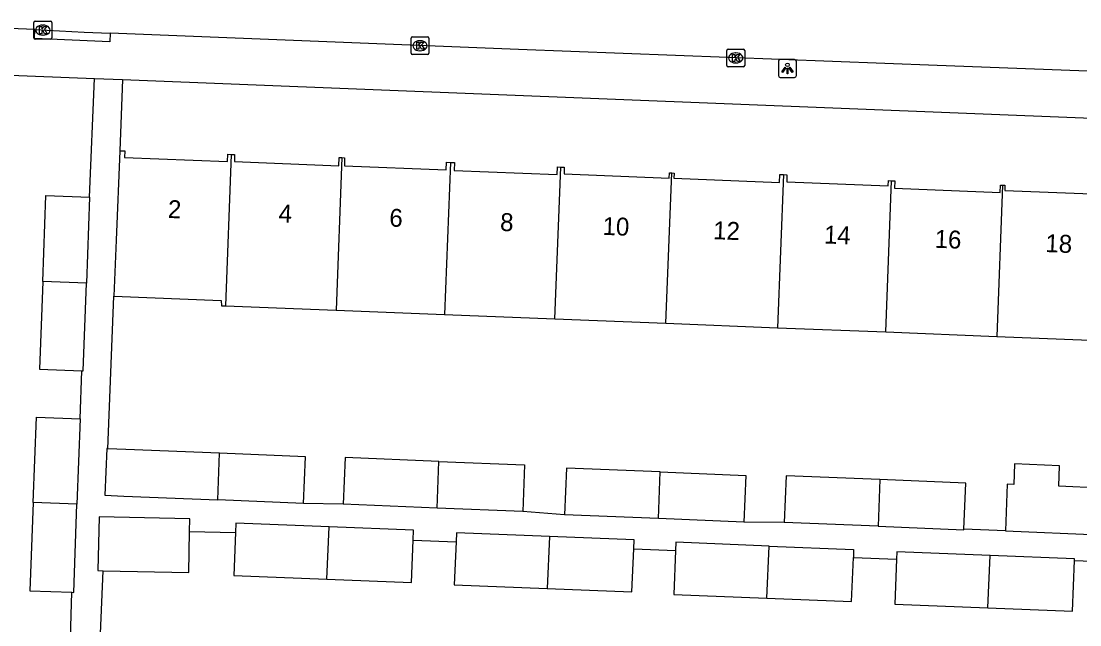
# Model space of a CAD drawing. Extents: x 160077 to 160945, y 386481 to 387498.
# Drawn here: x 160704.4 to 160763.6, y 386637.3 to 386671 of the extents above; entities that cross this region are included whole.
import ezdxf

# ---------------------------------------------------------------- set-up
doc = ezdxf.new("R2010")
doc.units = 0
for name, color, linetype in [('IMGEO_Kolk', 7, 'Continuous'), ('IMGEO_Lichtpunt', 7, 'Continuous'), ('IMGEO_Pand', 7, 'Continuous'), ('IMGEO_Pand_nummerreeks', 7, 'Continuous'), ('IMGEO_Rijbaan_lokaal_open', 7, 'Continuous'), ('IMGEO_Voetpad_open', 7, 'Continuous')]:
    doc.layers.add(name, color=color, linetype=linetype)

msp = doc.modelspace()

# ---------------------------------------------------------------- linework, layer by layer
at = {"layer": 'IMGEO_Kolk'}
for p, q in [((160705.154, 386670.106), (160705.154, 386670.958)), ((160705.229, 386671.032), (160706.081, 386671.032)), ((160705.642, 386670.812), (160705.667, 386670.812)), ((160706.155, 386670.958), (160706.155, 386670.106)), ((160705.665, 386670.252), (160705.64, 386670.252)), ((160726.213, 386669.238), (160726.213, 386670.09)), ((160726.288, 386670.164), (160727.14, 386670.164)), ((160727.214, 386670.09), (160727.214, 386669.238)), ((160706.081, 386670.032), (160705.229, 386670.032)), ((160726.701, 386669.944), (160726.726, 386669.944)), ((160743.922, 386669.479), (160744.774, 386669.479)), ((160727.14, 386669.164), (160726.288, 386669.164)), ((160726.724, 386669.384), (160726.699, 386669.384)), ((160743.847, 386668.553), (160743.847, 386669.405)), ((160744.335, 386669.259), (160744.36, 386669.259)), ((160744.848, 386669.405), (160744.848, 386668.553)), ((160744.774, 386668.479), (160743.922, 386668.479)), ((160744.358, 386668.699), (160744.333, 386668.699))]:
    msp.add_line(p, q, dxfattribs=at)
for points in [[(160705.154, 386670.106), (160705.154, 386670.958)], [(160705.229, 386671.032), (160706.081, 386671.032)], [(160705.475, 386670.732), (160705.598, 386670.732), (160705.598, 386670.581), (160705.728, 386670.732), (160705.892, 386670.732), (160705.746, 386670.581), (160705.899, 386670.332), (160705.747, 386670.332), (160705.662, 386670.496), (160705.598, 386670.429), (160705.598, 386670.332), (160705.475, 386670.332), (160705.475, 386670.732)], [(160706.155, 386670.958), (160706.155, 386670.106)], [(160726.213, 386669.238), (160726.213, 386670.09)], [(160726.288, 386670.164), (160727.14, 386670.164)], [(160727.214, 386670.09), (160727.214, 386669.238)], [(160706.081, 386670.032), (160705.229, 386670.032)], [(160726.534, 386669.864), (160726.657, 386669.864), (160726.657, 386669.713), (160726.787, 386669.864), (160726.951, 386669.864), (160726.805, 386669.713), (160726.958, 386669.464), (160726.806, 386669.464), (160726.721, 386669.628), (160726.657, 386669.561), (160726.657, 386669.464), (160726.534, 386669.464), (160726.534, 386669.864)], [(160743.922, 386669.479), (160744.774, 386669.479)], [(160727.14, 386669.164), (160726.288, 386669.164)], [(160743.847, 386668.553), (160743.847, 386669.405)], [(160744.168, 386669.179), (160744.291, 386669.179), (160744.291, 386669.028), (160744.421, 386669.179), (160744.585, 386669.179), (160744.439, 386669.028), (160744.592, 386668.779), (160744.44, 386668.779), (160744.355, 386668.943), (160744.291, 386668.876), (160744.291, 386668.779), (160744.168, 386668.779), (160744.168, 386669.179)], [(160744.848, 386669.405), (160744.848, 386668.553)], [(160744.774, 386668.479), (160743.922, 386668.479)]]:
    msp.add_lwpolyline(points, dxfattribs=at)
for centre, start, end in [((160705.231, 386670.956), 91.55205, 178.44795), ((160705.231, 386670.956), 91.55205, 178.44795), ((160706.079, 386670.956), 1.55205, 88.44795), ((160706.079, 386670.956), 1.55205, 88.44795), ((160705.231, 386670.108), 181.55205, 268.44795), ((160705.231, 386670.108), 181.55205, 268.44795), ((160706.079, 386670.108), 271.55205, 358.44795), ((160706.079, 386670.108), 271.55205, 358.44795), ((160726.29, 386670.088), 91.55205, 178.44795), ((160726.29, 386670.088), 91.55205, 178.44795), ((160727.138, 386670.088), 1.55205, 88.44795), ((160727.138, 386670.088), 1.55205, 88.44795), ((160743.924, 386669.403), 91.55205, 178.44795), ((160743.924, 386669.403), 91.55205, 178.44795), ((160744.772, 386669.403), 1.55205, 88.44795), ((160744.772, 386669.403), 1.55205, 88.44795), ((160726.29, 386669.24), 181.55205, 268.44795), ((160726.29, 386669.24), 181.55205, 268.44795), ((160727.138, 386669.24), 271.55205, 358.44795), ((160727.138, 386669.24), 271.55205, 358.44795), ((160743.924, 386668.555), 181.55205, 268.44795), ((160743.924, 386668.555), 181.55205, 268.44795), ((160744.772, 386668.555), 271.55205, 358.44795), ((160744.772, 386668.555), 271.55205, 358.44795)]:
    msp.add_arc(centre, 0.0765, start, end, dxfattribs=at)
for centre, major_axis, ratio, start_param, end_param in [((160705.641, 386670.532), (-0.387, 0.002), 0.722429, 4.712389, 7.853982), ((160705.666, 386670.532), (-0.39, 0.002), 0.717154, 1.570796, 4.712389), ((160726.7, 386669.664), (-0.387, 0.002), 0.722429, 4.712389, 7.853982), ((160726.725, 386669.664), (-0.39, 0.002), 0.717154, 1.570796, 4.712389), ((160744.334, 386668.979), (-0.387, 0.002), 0.722429, 4.712389, 7.853982), ((160744.359, 386668.979), (-0.39, 0.002), 0.717154, 1.570796, 4.712389)]:
    msp.add_ellipse(centre, major_axis=major_axis, ratio=ratio, start_param=start_param, end_param=end_param, dxfattribs=at)
at = {"layer": 'IMGEO_Lichtpunt'}
for p, q in [((160747.638, 386668.893), (160746.83, 386668.893)), ((160747.638, 386668.893), (160746.83, 386668.893)), ((160746.736, 386668.798), (160746.736, 386667.991)), ((160746.736, 386668.798), (160746.736, 386667.991)), ((160747.732, 386667.991), (160747.732, 386668.798)), ((160747.732, 386667.991), (160747.732, 386668.798)), ((160746.83, 386667.897), (160747.638, 386667.897)), ((160746.83, 386667.897), (160747.638, 386667.897))]:
    msp.add_line(p, q, dxfattribs=at)
for points in [[(160747.11, 386668.462), (160747.149, 386668.434), (160746.961, 386668.172), (160746.923, 386668.199), (160747.11, 386668.462)], [(160747.212, 386668.414), (160747.259, 386668.414), (160747.259, 386668.092), (160747.212, 386668.092), (160747.212, 386668.414)], [(160747.322, 386668.434), (160747.36, 386668.461), (160747.547, 386668.199), (160747.508, 386668.171), (160747.322, 386668.434)]]:
    msp.add_lwpolyline(points, dxfattribs=at)
msp.add_circle((160747.235, 386668.596), 0.0994, dxfattribs=at)
for centre, start, end in [((160746.83, 386668.798), 90, 180), ((160746.83, 386668.798), 90, 180), ((160747.638, 386668.798), 0, 90), ((160747.638, 386668.798), 0, 90), ((160746.83, 386667.991), 180, 270), ((160746.83, 386667.991), 180, 270), ((160747.638, 386667.991), 270, 0), ((160747.638, 386667.991), 270, 360)]:
    msp.add_arc(centre, 0.0946, start, end, dxfattribs=at)
at = {"layer": 'IMGEO_Pand'}
for points in [[(160709.948, 386663.799), (160709.748, 386658.803), (160709.624, 386655.676)], [(160709.948, 386663.799), (160710.224, 386663.788), (160710.21, 386663.426), (160715.964, 386663.197), (160715.98, 386663.605), (160716.172, 386663.598)], [(160716.172, 386663.598), (160715.845, 386655.138)], [(160716.172, 386663.598), (160716.364, 386663.59), (160716.348, 386663.197), (160722.191, 386662.964), (160722.209, 386663.427), (160722.358, 386663.418)], [(160722.358, 386663.418), (160722.028, 386654.895)], [(160722.358, 386663.418), (160722.506, 386663.409), (160722.503, 386662.965), (160728.184, 386662.738), (160728.201, 386663.156), (160728.42, 386663.148)], [(160728.42, 386663.148), (160728.092, 386654.655)], [(160728.42, 386663.148), (160728.641, 386663.139), (160728.624, 386662.705), (160734.371, 386662.476), (160734.388, 386662.9), (160734.582, 386662.892)], [(160734.253, 386654.412), (160734.582, 386662.892)], [(160734.582, 386662.892), (160734.773, 386662.885), (160734.759, 386662.513), (160740.632, 386662.278), (160740.644, 386662.563), (160740.775, 386662.558)], [(160740.45, 386654.168), (160740.775, 386662.558)], [(160740.775, 386662.558), (160740.905, 386662.553), (160740.894, 386662.269), (160746.791, 386662.034), (160746.809, 386662.48), (160747.01, 386662.472)], [(160747.01, 386662.472), (160746.679, 386653.922)], [(160747.01, 386662.472), (160747.209, 386662.464), (160747.193, 386662.058), (160752.858, 386661.833), (160752.87, 386662.135), (160753.05, 386662.128)], [(160752.723, 386653.684), (160753.05, 386662.128)], [(160753.05, 386662.128), (160753.231, 386662.12), (160753.215, 386661.713), (160759.118, 386661.478), (160759.134, 386661.871), (160759.252, 386661.87)], [(160759.252, 386661.87), (160758.926, 386653.439)], [(160759.252, 386661.87), (160759.369, 386661.869), (160759.369, 386661.58), (160765.188, 386661.36), (160765.2, 386661.664), (160765.398, 386661.657)], [(160705.647, 386656.499), (160705.823, 386661.297), (160708.266, 386661.207)], [(160708.266, 386661.207), (160708.09, 386656.408)], [(160705.647, 386656.499), (160705.468, 386651.604), (160707.83, 386651.517)], [(160708.09, 386656.408), (160705.647, 386656.499)], [(160707.83, 386651.517), (160707.911, 386651.514), (160708.09, 386656.408)], [(160709.624, 386655.676), (160715.62, 386655.437), (160715.628, 386655.147), (160715.845, 386655.138)], [(160715.845, 386655.138), (160722.028, 386654.895)], [(160722.028, 386654.895), (160728.092, 386654.655)], [(160728.092, 386654.655), (160734.253, 386654.412)], [(160734.253, 386654.412), (160740.45, 386654.168)], [(160740.45, 386654.168), (160746.679, 386653.922)], [(160746.679, 386653.922), (160752.723, 386653.684)], [(160752.723, 386653.684), (160758.926, 386653.439)], [(160758.926, 386653.439), (160765.07, 386653.196)], [(160705.114, 386644.158), (160705.289, 386648.93), (160707.732, 386648.84)], [(160707.732, 386648.84), (160707.557, 386644.067)], [(160709.274, 386647.168), (160709.22, 386647.17), (160709.112, 386644.566), (160710.178, 386644.522), (160715.426, 386644.305)], [(160715.527, 386646.91), (160710.285, 386647.126), (160709.274, 386647.168)], [(160715.426, 386644.305), (160715.527, 386646.91)], [(160720.205, 386644.108), (160720.312, 386646.712), (160715.527, 386646.91)], [(160727.775, 386646.46), (160722.533, 386646.676), (160722.426, 386644.072)], [(160727.675, 386643.855), (160727.775, 386646.46)], [(160727.775, 386646.46), (160732.56, 386646.262), (160732.453, 386643.658)], [(160740.129, 386645.87), (160734.888, 386646.086), (160734.781, 386643.482)], [(160740.028, 386643.265), (160740.129, 386645.87)], [(160740.129, 386645.87), (160744.915, 386645.672), (160744.808, 386643.068)], [(160764.751, 386644.969), (160762.383, 386645.067), (160762.43, 386646.212), (160759.919, 386646.316), (160759.872, 386645.17), (160759.511, 386645.185), (160759.404, 386642.581)], [(160752.404, 386645.44), (160747.163, 386645.656), (160747.056, 386643.052)], [(160752.404, 386645.44), (160752.303, 386642.835)], [(160757.085, 386642.677), (160757.19, 386645.242), (160752.404, 386645.44)], [(160705.114, 386644.158), (160704.934, 386639.237), (160707.268, 386639.151)], [(160707.557, 386644.067), (160705.114, 386644.158)], [(160707.268, 386639.151), (160707.377, 386639.147), (160707.557, 386644.067)], [(160720.205, 386644.108), (160715.426, 386644.305)], [(160727.675, 386643.855), (160722.426, 386644.072)], [(160732.453, 386643.658), (160727.675, 386643.855)], [(160740.028, 386643.265), (160734.781, 386643.482)], [(160713.85, 386642.544), (160713.865, 386643.258), (160708.79, 386643.362), (160708.729, 386640.362), (160709.029, 386640.356)], [(160721.634, 386642.804), (160716.434, 386643.01), (160716.414, 386642.492)], [(160744.808, 386643.068), (160740.028, 386643.265)], [(160752.303, 386642.835), (160747.056, 386643.052)], [(160709.029, 386640.356), (160713.804, 386640.258), (160713.85, 386642.544)], [(160716.414, 386642.492), (160716.319, 386640.097), (160721.512, 386639.891)], [(160721.512, 386639.891), (160721.634, 386642.804)], [(160726.335, 386642.06), (160726.357, 386642.616), (160721.634, 386642.804)], [(160733.946, 386642.268), (160728.746, 386642.474), (160728.726, 386641.965)], [(160752.303, 386642.835), (160757.083, 386642.638), (160757.085, 386642.677)], [(160759.404, 386642.581), (160764.65, 386642.364)], [(160721.512, 386639.891), (160726.242, 386639.703), (160726.335, 386642.06)], [(160728.726, 386641.965), (160728.631, 386639.561), (160733.824, 386639.355)], [(160733.946, 386642.268), (160733.824, 386639.355)], [(160738.649, 386641.573), (160738.669, 386642.08), (160733.946, 386642.268)], [(160746.209, 386641.734), (160741.01, 386641.94), (160740.992, 386641.481)], [(160746.087, 386638.821), (160746.209, 386641.734)], [(160746.209, 386641.734), (160750.933, 386641.546), (160750.915, 386641.089)], [(160733.824, 386639.355), (160738.554, 386639.167), (160738.649, 386641.573)], [(160740.992, 386641.481), (160740.895, 386639.027), (160746.087, 386638.821)], [(160758.548, 386641.198), (160753.349, 386641.404), (160753.333, 386640.994)], [(160758.426, 386638.285), (160758.548, 386641.198)], [(160763.269, 386640.93), (160763.272, 386641.01), (160758.548, 386641.198)], [(160746.087, 386638.821), (160750.818, 386638.633), (160750.915, 386641.089)], [(160753.333, 386640.994), (160753.234, 386638.491), (160758.426, 386638.285)], [(160758.426, 386638.285), (160763.157, 386638.097), (160763.269, 386640.93)]]:
    msp.add_lwpolyline(points, dxfattribs=at)
at = {"layer": 'IMGEO_Rijbaan_lokaal_open'}
for points in [[(160705.21, 386670.567), (160686.188, 386671.33)], [(160705.21, 386670.567), (160707.966, 386670.421), (160709.41, 386670.37)], [(160785.921, 386667.402), (160782.779, 386667.534), (160755.601, 386668.55), (160732.207, 386669.443), (160709.41, 386670.37)]]:
    msp.add_lwpolyline(points, dxfattribs=at)
at = {"layer": 'IMGEO_Voetpad_open'}
for points in [[(160709.41, 386670.37), (160709.387, 386669.871), (160705.187, 386670.068), (160705.21, 386670.567)], [(160685.945, 386668.735), (160708.53, 386667.837)], [(160708.266, 386661.207), (160708.53, 386667.837)], [(160708.53, 386667.837), (160710.106, 386667.774)], [(160710.106, 386667.774), (160709.948, 386663.799)], [(160710.106, 386667.774), (160784.298, 386664.825)], [(160709.274, 386647.168), (160709.624, 386655.676)], [(160707.732, 386648.84), (160707.83, 386651.517)], [(160722.426, 386644.072), (160720.205, 386644.108)], [(160734.781, 386643.482), (160732.453, 386643.658)], [(160747.056, 386643.052), (160744.808, 386643.068)], [(160713.85, 386642.544), (160716.414, 386642.492)], [(160759.404, 386642.581), (160757.085, 386642.677)], [(160726.335, 386642.06), (160728.726, 386641.965)], [(160738.649, 386641.573), (160740.992, 386641.481)], [(160750.915, 386641.089), (160753.333, 386640.994)], [(160763.269, 386640.93), (160765.729, 386640.833)], [(160708.673, 386632.054), (160709.029, 386640.356)], [(160707.192, 386636.59), (160707.268, 386639.151)]]:
    msp.add_lwpolyline(points, dxfattribs=at)

# ---------------------------------------------------------------- texts
at = {"layer": 'IMGEO_Pand_nummerreeks'}
for s, p in [('2', (160712.621, 386660.05)), ('4', (160718.806, 386659.81)), ('6', (160724.989, 386659.57)), ('8', (160731.176, 386659.329)), ('10', (160736.898, 386659.107)), ('12', (160743.075, 386658.867)), ('14', (160749.261, 386658.626)), ('16', (160755.443, 386658.386)), ('18', (160761.629, 386658.146))]:
    msp.add_text(s, height=1, rotation=357.77452, dxfattribs=at).set_placement(p)

doc.saveas('drawing.dxf')
